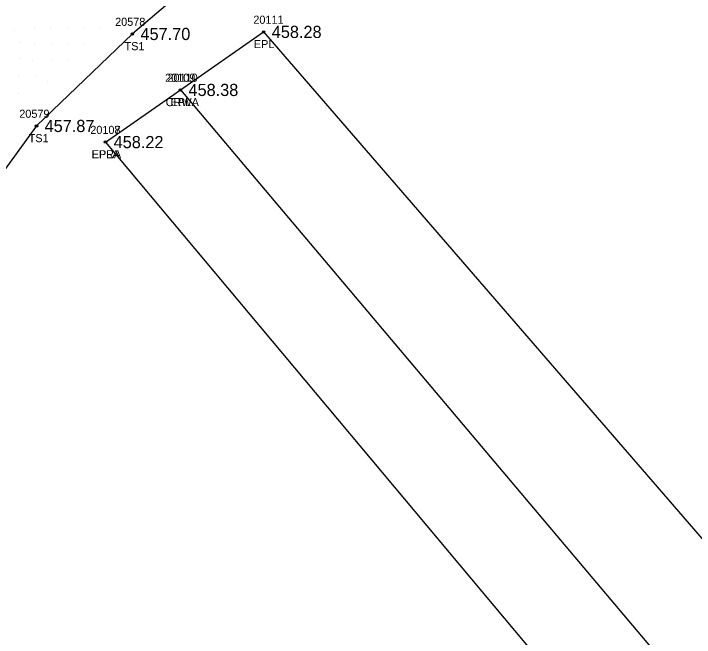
# Model space of a CAD drawing. Extents: x 1747760 to 1751131, y 649333 to 653784.
# Drawn here: x 1749239.9 to 1749323.7, y 651202.5 to 651279.3 of the extents above; entities that cross this region are included whole.
import ezdxf

# ---------------------------------------------------------------- set-up
doc = ezdxf.new("R2010")
doc.units = 0
for name, color, linetype in [('RD_DTM_BkLn1', 7, 'Continuous'), ('RD_DTM_BkLn2', 7, 'Continuous'), ('RD_DTM_BkLn_txCode', 7, 'Continuous'), ('RD_DTM_Spot', 7, 'Continuous'), ('RD_EX_Road', 7, 'Continuous'), ('RD_EX_Road_txCode', 7, 'Continuous'), ('RD_EX_TX_Misc_ELEV', 7, 'Continuous'), ('RD_EX_TX_Road_ELEV', 7, 'Continuous'), ('RD_HC_Survey_ELEV', 7, 'Continuous'), ('RD_HC_Survey_txCode', 7, 'Continuous'), ('RD_SMD_Locator', 7, 'Continuous')]:
    doc.layers.add(name, color=color, linetype=linetype)

msp = doc.modelspace()

# ---------------------------------------------------------------- linework, layer by layer
at = {"layer": 'RD_DTM_BkLn1'}
msp.add_lwpolyline([(1749260.448, 651269.918), (1749320.561, 651198.681)], dxfattribs=at)
at = {"layer": 'RD_DTM_BkLn2'}
msp.add_lwpolyline([(1749334.274, 651347.939), (1749311.737, 651326.42), (1749292.613, 651306.019), (1749271.131, 651290.935), (1749254.537, 651276.811), (1749242.73, 651265.483), (1749232.71, 651251.743), (1749211.561, 651228.743), (1749190.496, 651216.053), (1749178.766, 651203.369)], dxfattribs=at)
at = {"layer": 'RD_DTM_Spot'}
for p, q in [((1749242.508, 651277.606), (1749242.508, 651277.606)), ((1749244.476, 651277.646), (1749244.476, 651277.646)), ((1749246.552, 651277.636), (1749246.552, 651277.636)), ((1749248.499, 651277.587), (1749248.499, 651277.587)), ((1749250.571, 651277.596), (1749250.571, 651277.596)), ((1749240.083, 651277.204), (1749240.083, 651277.204)), ((1749240.658, 651275.79), (1749240.658, 651275.79)), ((1749244.585, 651275.645), (1749244.585, 651275.645)), ((1749246.567, 651275.652), (1749246.567, 651275.652)), ((1749242.532, 651275.514), (1749242.532, 651275.514)), ((1749248.561, 651275.567), (1749248.561, 651275.567)), ((1749240.632, 651273.843), (1749240.632, 651273.843)), ((1749242.246, 651273.531), (1749242.246, 651273.531)), ((1749244.538, 651273.55), (1749244.538, 651273.55)), ((1749246.602, 651273.583), (1749246.602, 651273.583)), ((1749240.546, 651271.628), (1749240.546, 651271.628)), ((1749242.642, 651271.515), (1749242.642, 651271.515)), ((1749244.053, 651270.965), (1749244.053, 651270.965)), ((1749240.528, 651269.485), (1749240.528, 651269.485))]:
    msp.add_line(p, q, dxfattribs=at)
at = {"layer": 'RD_EX_Road'}
for points in [[(1749251.231, 651263.495), (1749260.448, 651269.918), (1749270.704, 651277.064), (1749331.28, 651207.039), (1749394.892, 651131.098)], [(1749251.231, 651263.495), (1749312.598, 651190.195)]]:
    msp.add_lwpolyline(points, dxfattribs=at)
at = {"layer": 'RD_SMD_Locator'}
for centre in [(1749254.537, 651276.811), (1749270.704, 651277.064), (1749260.448, 651269.918), (1749260.448, 651269.918), (1749242.73, 651265.483), (1749251.231, 651263.495), (1749251.231, 651263.495)]:
    msp.add_circle(centre, 0.15, dxfattribs=at)

# ---------------------------------------------------------------- texts
at = {"layer": 'RD_DTM_BkLn_txCode'}
for s, p in [('20578', (1749252.418, 651277.811)), ('TS1', (1749253.576, 651274.811)), ('20579', (1749240.612, 651266.483)), ('TS1', (1749241.769, 651263.483))]:
    msp.add_text(s, height=1, dxfattribs=at).set_placement(p)
at = {"layer": 'RD_EX_Road_txCode'}
for s, p in [('20111', (1749269.436, 651278.064)), ('EPL', (1749269.499, 651275.064)), ('20109', (1749258.574, 651270.918)), ('EPL', (1749259.244, 651267.918)), ('20107', (1749249.357, 651264.495)), ('20108', (1749249.357, 651264.495)), ('EPRA', (1749249.515, 651261.495)), ('EPLA', (1749249.538, 651261.495))]:
    msp.add_text(s, height=1, dxfattribs=at).set_placement(p)
at = {"layer": 'RD_EX_TX_Misc_ELEV'}
for s, p in [('457.70', (1749255.537, 651276.061)), ('457.87', (1749243.73, 651264.733))]:
    msp.add_text(s, height=1.5, dxfattribs=at).set_placement(p)
at = {"layer": 'RD_EX_TX_Road_ELEV'}
for s, p in [('458.28', (1749271.704, 651276.314)), ('458.38', (1749261.448, 651269.168)), ('458.22', (1749252.231, 651262.745)), ('458.22', (1749252.231, 651262.745))]:
    msp.add_text(s, height=1.5, dxfattribs=at).set_placement(p)
at = {"layer": 'RD_HC_Survey_ELEV'}
msp.add_text('458.38', height=1.5, dxfattribs=at).set_placement((1749261.448, 651269.168))
at = {"layer": 'RD_HC_Survey_txCode'}
for s, p in [('20110', (1749258.858, 651270.918)), ('CRWA', (1749258.645, 651267.918))]:
    msp.add_text(s, height=1, dxfattribs=at).set_placement(p)

doc.saveas('drawing.dxf')
